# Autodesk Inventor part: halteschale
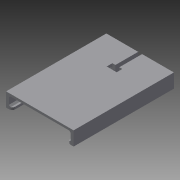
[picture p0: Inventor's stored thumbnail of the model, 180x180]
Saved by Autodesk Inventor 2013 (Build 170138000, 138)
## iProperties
Created: 2013-04
Part Number: halteschale
Material: Allgemein
Document SubType Name: Modeling
Designer: md
Density: 1 g/cm^3
d0: 1.000 ul
d1: 3,000 mm
d2: 3,000 mm
d4: 3,000 mm
d12: 75.000 mm
d13: 66,000 mm
d14: 0.00 deg
d15: 1,500 mm
d16: 1,500 mm
d17: 1,500 mm
d18: 7,000 mm
d19: 7,000 mm
d20: 7,000 mm
d21: 3,000 mm
d32: 0.00 deg
d47: 0.750 mm
d50: 20,000 mm
d51: 0.00 deg
d52: 1.000 ul
d53: 0,000 mm
d54: 3,500 mm
d55: -68,500 mm
d59: 28,125 mm
d60: 62,500 mm
d62: 0.00 deg
d63: 5,500 mm
Halteschale_Arme_Dicke: 3,000 mm
Halteschale_Arme_Freistellung: 1,500 mm
d3: 124,000 mm
d22: 59,000 mm
d24: 124,000 mm
d25: 8,000 mm
d26: 8,000 mm
d27: 8,000 mm
d28: 7,700 mm
d29: 0.00 deg
d30: 17,000 mm
d31: 4,000 mm
Homebutton_Durchmesser: 11,000 mm
d33: 8,500 mm
d34: 29,500 mm
d35: 11,000 mm
d36: 2,500 mm
d37: 5,000 mm
d38: 2,500 mm
d39: 2,750 mm
d40: 9,500 mm
d41: 3,400 mm
d42: 0,500 mm
d43: 4,300 mm
d44: 12,000 mm
d49: 1,000 mm
Grundkoerper_Breite: 59,000 mm
Grundkoerper_Hoehe: 124,000 mm
Grundkoerper_Dicke: 7,700 mm
Grundkoerper_Rundung_Radius: 8,000 mm
Author: md
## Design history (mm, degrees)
derived "iphone.ipt" dims count "d0" = 1
  sketch "Vorderseite"
    geometry: L1 (-5.533, 49.978)-(5.467, 49.978) reference; L2 (5.467, 49.978)-(5.467, 52.478) reference; L3 (5.467, 52.478)-(-5.533, 52.478) reference; L4 (-5.533, 52.478)-(-5.533, 49.978) reference; L5 (-5.533, 49.978)-(5.467, 52.478) reference; L6 (5.467, 49.978)-(-5.533, 52.478) reference; L7 (-0.033, 61.978)-(-0.033, -62.022) reference; L8 (29.467, 53.978)-(29.467, -54.022) reference; L9 (-21.533, 61.978)-(21.467, 61.978) reference; L10 (-29.533, -54.022)-(-29.533, 53.978) reference; L11 (21.467, -62.022)-(-21.533, -62.022) reference; L12 (29.467, 53.978)-(29.467, -54.022) reference; L13 (-21.533, 61.978)-(21.467, 61.978) reference; L14 (-29.533, -54.022)-(-29.533, 53.978) reference; L15 (21.467, -62.022)-(-21.533, -62.022) reference; L16 (-25.533, -44.978)-(25.533, -44.978) reference; L17 (25.533, -44.978)-(25.533, 44.978) reference; L18 (25.533, 44.978)-(-25.533, 44.978) reference; L19 (-25.533, 44.978)-(-25.533, -44.978) reference; L20 (-25.533, -44.978)-(25.533, 44.978) reference; L21 (25.533, -44.978)-(-25.533, 44.978) reference; C1 r 1.25 at (-0.033, 56.478) reference; C2 r 5.5 at (-0.033, -53.522) reference; A1 r 8 centre (21.467, 53.978) between (29.467, 53.978) and (21.467, 61.978) reference; A2 r 8 centre (-21.533, 53.978) between (-21.533, 61.978) and (-29.533, 53.978) reference; A3 r 8 centre (-21.533, -54.022) between (-29.533, -54.022) and (-21.533, -62.022) reference; A4 r 8 centre (21.467, -54.022) between (21.467, -62.022) and (29.467, -54.022) reference; A5 r 8 centre (21.467, 53.978) between (29.467, 53.978) and (21.467, 61.978) reference; A6 r 8 centre (-21.533, 53.978) between (-21.533, 61.978) and (-29.533, 53.978) reference; A7 r 8 centre (-21.533, -54.022) between (-29.533, -54.022) and (-21.533, -62.022) reference; A8 r 8 centre (21.467, -54.022) between (21.467, -62.022) and (29.467, -54.022) reference; 3 further points
  sketch "Unterseite"
    geometry: L1 (43, 0)-(43, 7.7) reference; L2 (0, 7.7)-(43, 7.7) reference; L3 (0, 0)-(0, 7.7) reference; L4 (21.467, 0)-(21.5, 7.7) reference; L5 (0, 3.85)-(43, 3.85) reference; L6 (17.25, 2.15)-(25.75, 2.15) reference; L7 (26.25, 2.65)-(26.25, 5.05) reference; L8 (25.75, 5.55)-(17.25, 5.55) reference; L9 (16.75, 5.05)-(16.75, 2.65) reference; L10 (16.75, 2.15)-(26.25, 5.55) reference; L11 (26.25, 2.15)-(16.75, 5.55) reference; C1 r 2.15 at (40.4, 3.85) reference; A1 r 0.5 centre (17.25, 5.05) between (17.25, 5.55) and (16.75, 5.05) reference; A2 r 0.5 centre (25.75, 5.05) between (26.25, 5.05) and (25.75, 5.55) reference; A3 r 0.5 centre (25.75, 2.65) between (25.75, 2.15) and (26.25, 2.65) reference; A4 r 0.5 centre (17.25, 2.65) between (16.75, 2.65) and (17.25, 2.15) reference; 1 further point
sketch "Skizze5"
  geometry: L1 (1, 61.978)-(6.7, 61.978) reference; L2 (0, 60.978)-(1, 61.978) reference; L3 (0, 53.978)-(0, 60.978) reference; L4 (0, 53.978)-(0, -54.022) reference; L5 (6.7, 61.978)-(7.7, 60.978) reference; L6 (7.7, 60.978)-(7.7, 53.978) reference; L7 (7.7, -54.022)-(7.7, 53.978) reference; L8 (0, -61.022)-(0, -54.022) reference; L9 (0, -61.022)-(1, -62.022) reference; L10 (1, -62.022)-(6.7, -62.022) reference; L11 (6.7, -62.022)-(7.7, -61.022) reference; L12 (7.7, -54.022)-(7.7, -61.022) reference; L13 (0, -44.978)-(10.7, -44.978); L14 (0, -54.022)-(10.7, -54.022); L15 (-3, -65.022)-(10.7, -65.022); L16 (10.7, -65.022)-(10.7, 12.978); L17 (10.7, 12.978)-(-3, 12.978); L18 (-3, 12.978)-(-3, -65.022); 4 further points
  constraints: 12 end point, 4 parallel, 2 perpendicular, 2 point on line, 1 horizontal
  dimensions: "d1" = 3 distance between parallel lines of L4 L18 (= Halteschale_Arme_Dicke); "d2" = 3 distance between parallel lines of L16 L7 (= Halteschale_Arme_Dicke); "d4" = 3 distance between parallel lines of L10 L15 (= Halteschale_Arme_Dicke); "d12" = 75 distance between parallel lines of L10 L17
extrude "Grundkoerper" new body sketch "Skizze5" stored distance "d13" = 66 (computed from Halteschale_Arme_Dicke, Grundkoerper_Breite); taper "d14" = 0 deg
feature "Innerer Ausschnitt"
  node "Volumenkörper1"
sketch "Skizze6"
  geometry: L1 (66, 0)-(0, 0) reference; L2 (66, 78)-(66, 0) reference; L3 (0, 78)-(66, 78) reference; L4 (0, 0)-(0, 78) reference; L5 (58.533, 20.045)-(58.533, 110) reference; L6 (7.467, 110)-(7.467, 20.045) reference; L7 (7.467, 20.045)-(58.533, 20.045) reference; L8 (5.967, 75)-(5.967, 21.545); L9 (8.967, 18.545)-(22.967, 18.545); L10 (25.967, 15.545)-(25.967, 7.5); L11 (28.967, 4.5)-(36.967, 4.5); L12 (39.967, 7.5)-(39.967, 15.545); L13 (42.967, 18.545)-(57.033, 18.545); L14 (60.033, 21.545)-(60.033, 75); L15 (5.967, 78)-(60.033, 78); L16 (2.967, 78)-(0, 78); L17 (63.033, 78)-(66, 78); C1 r 5.5 at (32.967, 11.5) reference; A1 r 3 centre (2.967, 75) between (5.967, 75) and (2.967, 78); A2 r 3 centre (63.033, 75) between (63.033, 78) and (60.033, 75); A3 r 3 centre (57.033, 21.545) between (57.033, 18.545) and (60.033, 21.545); A4 r 3 centre (42.967, 15.545) between (42.967, 18.545) and (39.967, 15.545); A5 r 3 centre (36.967, 7.5) between (36.967, 4.5) and (39.967, 7.5); A6 r 3 centre (28.967, 7.5) between (25.967, 7.5) and (28.967, 4.5); A7 r 3 centre (22.967, 15.545) between (25.967, 15.545) and (22.967, 18.545); A8 r 3 centre (8.967, 21.545) between (5.967, 21.545) and (8.967, 18.545); 1 further point
  constraints: 20 end point, 16 point on circle, 16 tangent, 8 centre point, 7 equal radius, 6 point on line, 4 collinear, 4 perpendicular, 3 parallel
  dimensions: "d15" = 1.5 distance between parallel lines of L6 L8 (= Halteschale_Arme_Freistellung); "d16" = 1.5 distance between parallel lines of L14 L5 (= Halteschale_Arme_Freistellung); "d17" = 1.5 distance between parallel lines of L7 L9 (= Halteschale_Arme_Freistellung); "d18" = 7 distance from line of C1.centre L10 (= 0.5 x Homebutton_Durchmesser + Halteschale_Arme_Freistellung); "d19" = 7 distance from line of C1.centre L12 (= d18); "d20" = 7 distance from line of C1.centre L11 (= d18); "d21" = 3 radius of A1
extrude "Ausschnitt_Vorne" cut sketch "Skizze6" stored distance "d23" = 65 (= Grundkoerper_Breite + 2 x Halteschale_Arme_Dicke); taper "d32" = 0 deg
feature "Freistellung_Ausschnitt" dims "d47" = 0.75, "d48" = 0.5
sketch "Skizze8"
  geometry: L1 (66, 0)-(0, 0) reference; L2 (0, -13.7)-(0, 0) reference; L3 (0, -13.7)-(66, -13.7) reference; L4 (66, 0)-(66, -13.7) reference; L5 (66, 0)-(0, 0) reference; L6 (0, -13.7)-(0, 0) reference; L7 (0, -13.7)-(66, -13.7) reference; L8 (66, 0)-(66, -13.7) reference; 1 further point
extrude "Extrusion4" join sketch "Skizze8" distance "d50" = 20; taper "d51" = 0 deg
derived "lightning_kabel_apple_orig.ipt" dims count "d52" = 1
  sketch "Skizze1"
    geometry: L1 (-3.875, -6.05)-(3.875, -6.05) reference; L2 (3.875, -6.05)-(3.875, 6.05) reference; L3 (3.875, 6.05)-(-3.875, 6.05) reference; L4 (-3.875, 6.05)-(-3.875, -6.05) reference; L5 (-3.875, -6.05)-(3.875, 6.05) reference; L6 (3.875, -6.05)-(-3.875, 6.05) reference; L7 (1.9, -6.05)-(-1.9, -6.05) reference; L8 (0, 6.05)-(0, -46.05) reference; L9 (0, -46.05)-(1.9, -46.05) reference; L10 (1.9, -46.05)-(1.9, -6.05) reference; L11 (1.9, -6.05)-(0, -6.05) reference; L12 (0, -6.05)-(0, -46.05) reference; 3 further points
sketch "Skizze10"
  geometry: L1 (7.75, -4.7)-(7.75, 0) reference; L2 (0, 0)-(7.75, 0) reference; L3 (0, -4.7)-(0, 0) reference; L4 (7.75, -4.7)-(0, -4.7) reference; L5 (7.75, 0)-(0, -4.7); L6 (0, 0)-(7.75, -4.7); 1 further point
  constraints: 4 end point
feature "Körper verschieben1"
feature "Ausschnitt_Kabel"
  node "Volumenkörper3"
sketch "Skizze11"
  geometry: L1 (66, 0)-(66, 98) reference; L2 (0, 98)-(66, 98) reference; L3 (31.1, 87.528)-(31.1, 98) reference; L4 (34.9, 87.528)-(34.9, 98) reference; L5 (33, 98)-(33, 12.978); L6 (37.875, 88.778)-(37.875, 74.75); L7 (37.875, 74.75)-(28.125, 74.75); L8 (28.125, 74.75)-(28.125, 88.778); L9 (28.125, 88.778)-(37.875, 88.778); L10 (37.875, 75.75)-(37.875, 70.25); L11 (37.875, 70.25)-(28.125, 70.25); L12 (28.125, 70.25)-(28.125, 75.75); L13 (31.1, 87.528)-(31.1, 75.75); L14 (34.9, 87.528)-(34.9, 75.75); L15 (34.9, 77.528)-(34.9, 98); L16 (34.9, 98)-(31.1, 98); L17 (31.1, 98)-(31.1, 87.528); L18 (28.125, 75.75)-(31.1, 75.75); L19 (34.9, 75.75)-(37.875, 75.75); L20 (54.467, 75.75)-(11.467, 75.75) reference; 2 further points
  constraints: 30 end point, 4 parallel, 3 perpendicular, 2 collinear, 2 horizontal, 1 midpoint, 1 point on line
  dimensions: "d59" = 28.125 distance between parallel lines of L1 L10; "d63" = 5.5 distance between parallel lines of L18 L11
extrude "Extrusion5" cut sketch "Skizze11" stored distance "d61" = 30; taper "d62" = 0 deg
sketch "Sketch12"
  geometry: L1 (25.408, 5.161)-(25.408, 0.461) reference; L2 (25.408, 0.461)-(17.658, 0.461) reference; L3 (17.658, 0.461)-(17.658, 5.161) reference; L4 (17.658, 2.811)-(25.408, 2.811); L5 (21.533, 0.461)-(21.533, 2.811); L6 (17.608, 0.361)-(25.458, 0.361); L7 (25.458, 0.361)-(25.458, 5.261); L8 (25.458, 5.261)-(17.608, 5.261); L9 (17.608, 5.261)-(17.608, 0.361); L10 (17.608, 0.361)-(25.458, 5.261); L11 (25.458, 0.361)-(17.608, 5.261); 1 further point
  constraints: 16 end point, 6 midpoint, 2 parallel, 1 horizontal, 1 perpendicular
  dimensions: "d64" = 7.85 distance of L8.end L7.end; "d65" = 4.9 distance of L7.end L6.end
extrude "Extrusion6" cut sketch "Sketch12" stored distance "d66" = 10; taper "d67" = 0 deg
feature "Solid1::iphone.ipt" dims count "d0" = 1
tag "Bezeichnung1"
node "Volumenkörper2"
node "Projizierte Kontur1"
feature "Volumenkörper1::lightning_kabel_apple_orig.ipt" dims count "d52" = 1
tag "Bezeichnung2"
other parameters: "d3" = 124, "d22" = 59, "d24" = 124, "d25" = 8, "d26" = 8, "d27" = 8, "d28" = 7.7, "d29" = 0 deg, "d30" = 17, "d31" = 4, "Homebutton_Durchmesser" = 11, "d33" = 8.5, "d34" = 29.5, "d35" = 11, "d36" = 2.5, "d37" = 5, "d38" = 2.5, "d39" = 2.75, "d40" = 9.5, "d41" = 3.4, "d42" = 0.5, "d43" = 4.3, "d44" = 12, "d49" = 1, "Grundkoerper_Breite" = 59, "Grundkoerper_Hoehe" = 124, "Grundkoerper_Dicke" = 7.7, "Grundkoerper_Rundung_Radius" = 8, "Halteschale_Arme_Dicke" = 3 [user parameter; used in 5 equation terms], "Halteschale_Arme_Freistellung" = 1.5 [user parameter; used in 4 equation terms], "d53" = 0, "d54" = 3.5, "d55" = -68.5, "d60" = 62.5
